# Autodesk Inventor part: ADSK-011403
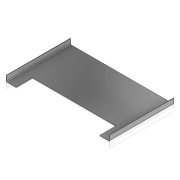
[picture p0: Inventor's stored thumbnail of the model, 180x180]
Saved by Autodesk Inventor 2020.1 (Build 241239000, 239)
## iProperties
Created: 2000-01
Part Number: ADSK-011403
Material: 1.0312 DC05
Document SubType Name: Tôlerie
Designer: glanglot
Density: 1 g/cm^3
Sheet Metal Rule: Stahlblech 1.0312 - DC05 -   1.5mm
Appearance: Chrom - poliert
Mass: 53.1381 g
Surface Area: 722.753 cm^2
Volume: 53.1381 cm^3
Sheet Metal Width: 157,000 mm
Sheet Metal Length: 277,586 mm
Sheet Metal Area: 43580,977 mm^2
Flat Pattern Width: 15.7 cm
Flat Pattern Length: 27.7586 cm
Flat Pattern Area: 435.81 cm^2
Control State: 0
Master: False
Checked Out: False
Shininess: 57.0
Length Units: 11269
Angle Units: 11279
Time Units: 11290
Mass Units: 11283
Length Display Precision: 3
Angle Display Precision: 2
Compacted: True
CUTLENGTH: 6.13 X 10.91 (67 SI)
MATERIAL DESC: SHEET,S/S, 16 GA
MATERIAL_NUMBER: A084639
G_L: 277,6x157 mm
Thickness: 1,500 mm
Dimensions: 254,8x14x157 mm
Mass: 0,053 kg
Semi finished: Stahlblech 1.0312 - DC05 -   1.5mm
DocNumber: ADSK-011403.ipt
Folder: 01 - Themengebiete\Simplification\01 - Packaging machine\
VDS_Category: 3D Komponenten
Density: 8.03
Volumn: 54.76905292465652
Area: 705.0654502018685
PropertySet Name: Model Information
Author: glanglot
Revision Number: -
Title: box
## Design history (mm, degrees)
node "Solide1"
  node "Konturlasche1"
sketch "Sketch1"
  geometry: L1 (127.4, 14)-(127.4, 0); L2 (127.4, 0)-(-127.4, 0); L3 (-127.4, 0)-(-127.4, 14); L4 (0, 0)-(0, 35.031); 1 further point
  constraints: 8 end point, 1 coincident, 1 midpoint
  dimensions: "d8" = 254.8 distance between parallel lines of L1 L3; "d14" = 14 distance of L1.start L1.end
sketch "Sketch2"
  geometry: L1 (23.313, -39.25)-(23.313, -79.25); L2 (228.312, -39.25)-(23.313, -39.25); L3 (228.312, -79.25)-(228.312, -39.25); L4 (228.312, -79.25)-(23.313, -79.25); L5 (1.412, -79.25)-(250.213, -79.25) reference; 2 further points
  constraints: 8 end point, 2 horizontal, 2 midpoint, 2 perpendicular, 1 coincident, 1 collinear
  dimensions: "d26" = 40 distance of L3.start L2.start; "d27" = 205 distance of L2.start L1.start
feature "Ecke1" dims "d22" = 1.5, "d23" = 6 (= CornerReliefSize), "d24" = 1.5 (= TailleJeu), "d25" = 1.5 (= TailleRayonJacobi)
feature "Ausklinkung1" dims "d28" = 1.5 (= Thickness), "d29" = 0
feature "Grobblech1" dims "d15" = 1.5 (= Thickness), "d16" = 1.5 (= BendReliefWidth), "d17" = 0.75 (= BendReliefDepth), "d18" = 3 (= MinimumRemnant), "d19" = 1.5 (= TransitionRadius), "d20" = 157, "d21" = 1.5 (= BendRadius), "d22" = 1.5, "d23" = 6 (= CornerReliefSize), "d24" = 1.5 (= TailleJeu), "d25" = 1.5 (= TailleRayonJacobi), "SeamGap" = 0.00508
feature "Biegung1" dims "d15" = 1.5 (= Thickness), "d16" = 1.5 (= BendReliefWidth), "d17" = 0.75 (= BendReliefDepth), "d18" = 3 (= MinimumRemnant), "d19" = 1.5 (= TransitionRadius), "d21" = 1.5 (= BendRadius), "d22" = 1.5, "SeamGap" = 0.00508
node "Corps solides"
node "Corps surfaciques"
feature "Definition1"
other parameters: "Thickness" = 1.5 (derived), "BendRadius" = 1.5 (= Thickness), "BendReliefWidth" = 1.5 (= Thickness), "BendReliefDepth" = 0.75 (= 0.5 x Thickness), "CornerReliefSize" = 6 (= 4 x Thickness), "MinimumRemnant" = 3 (= 2 x Thickness), "TransitionRadius" = 1.5 (= BendRadius), "TailleRayonJacobi" = 1.5 (= BendRadius), "TailleJeu" = 1.5 (= Thickness), "BendRadius" = 1.5, "BendReliefDepth" = 0.75, "BendReliefWidth" = 1.5, "CornerReliefSize" = 6, "MinimumRemnant" = 3, "TailleJeu" = 1.5, "TailleRayonJacobi" = 1.5, "Thickness" = 1.5, "TransitionRadius" = 1.5
